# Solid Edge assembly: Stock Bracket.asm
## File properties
Author: CADCIM
Template: ansi assembly.asm
Last saved by: SOFT
Revision: 12
Application: Solid Edge
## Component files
support_roller_bracket.par
stock_support_roller.par
adjusting_nut_handle.par
adjusting_screw_guide.par
Stock_support_base.par
thrust_bearing.par
adjusting_screw_nut.par
support_adjusting_screw.par
